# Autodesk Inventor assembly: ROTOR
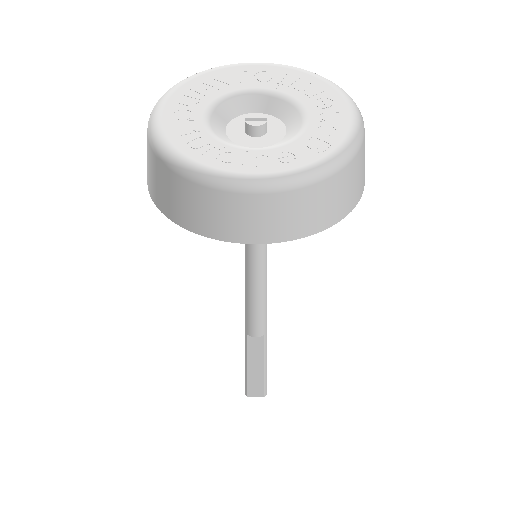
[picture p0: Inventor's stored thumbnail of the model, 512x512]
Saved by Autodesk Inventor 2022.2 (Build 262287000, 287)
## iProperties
Created: 2025-01
Part Number: ROTOR
Document SubType Name: Assembly
Designer: 18907419
Author: 18907419
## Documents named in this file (4)
- C:\Users\18907419\Desktop\mini\Creo\ROTOR.iam
- C:\Users\18907419\Desktop\mini\Creo\CHAPEAU.ipt
- C:\Users\18907419\Desktop\mini\Creo\AIMANT.ipt
- C:\Users\18907419\Desktop\mini\Creo\AXE_ROTOR.ipt
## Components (3 placed, 3 different names)
1. CHAPEAU
2. AIMANT
3. AXE_ROTOR
